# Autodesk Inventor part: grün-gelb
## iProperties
Created: 2004-10
Part Number: grün-gelb
Document SubType Name: Modeling
Designer: sahrens
Manufacturer: Standard
Standards Organization: Custom
Author: sahrens
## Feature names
1. Extrusion1
2. Rundung2 [Fillet]
